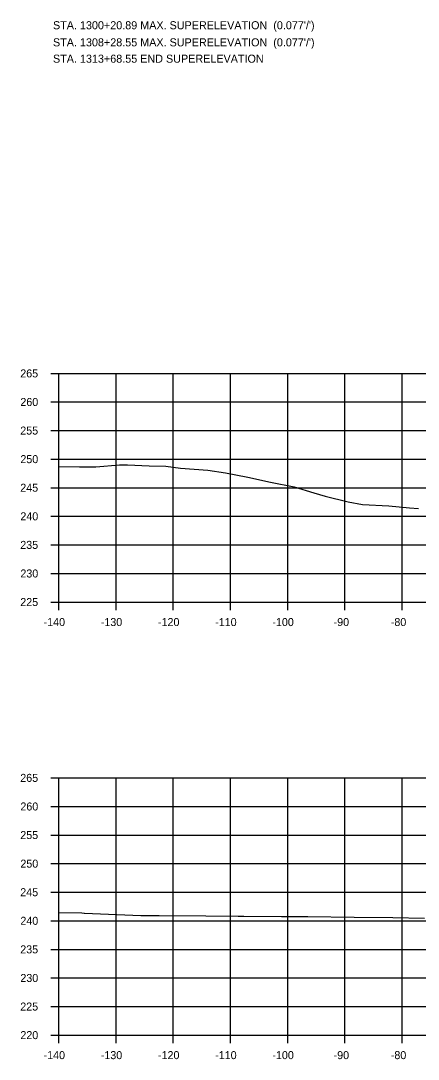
# Model space of a CAD drawing. Extents: x 1342547 to 1344156, y -1532351 to -1517216.
# Drawn here: x 1342556.2 to 1342625.7, y -1520815.1 to -1520633.5 of the extents above; entities that cross this region are included whole.
import ezdxf

# ---------------------------------------------------------------- set-up
doc = ezdxf.new("R2010")
doc.units = 0
for name, color, linetype in [('R_Axis', 7, 'Continuous'), ('R_Axis Annot', 7, 'Continuous'), ('R_Border Notes', 7, 'Continuous'), ('R_Exist Surface', 7, 'Continuous'), ('R_Grid', 7, 'Continuous')]:
    doc.layers.add(name, color=color, linetype=linetype)

msp = doc.modelspace()

# ---------------------------------------------------------------- linework, layer by layer
at = {"layer": 'R_Axis'}
for p, q in [((1342561.47, -1520695.14), (1342562.87, -1520695.14)), ((1342562.87, -1520735.14), (1342562.87, -1520695.14)), ((1342561.47, -1520700.14), (1342562.87, -1520700.14)), ((1342561.47, -1520705.14), (1342562.87, -1520705.14)), ((1342561.47, -1520710.14), (1342562.87, -1520710.14)), ((1342561.47, -1520715.14), (1342562.87, -1520715.14)), ((1342561.47, -1520720.14), (1342562.87, -1520720.14)), ((1342561.47, -1520725.14), (1342562.87, -1520725.14)), ((1342561.47, -1520730.14), (1342562.87, -1520730.14)), ((1342561.47, -1520735.14), (1342562.87, -1520735.14)), ((1342562.87, -1520735.14), (1342842.87, -1520735.14)), ((1342562.87, -1520736.54), (1342562.87, -1520735.14)), ((1342572.87, -1520736.54), (1342572.87, -1520735.14)), ((1342582.87, -1520736.54), (1342582.87, -1520735.14)), ((1342592.87, -1520736.54), (1342592.87, -1520735.14)), ((1342602.87, -1520736.54), (1342602.87, -1520735.14)), ((1342612.87, -1520736.54), (1342612.87, -1520735.14)), ((1342622.87, -1520736.54), (1342622.87, -1520735.14)), ((1342561.47, -1520765.9), (1342562.87, -1520765.9)), ((1342562.87, -1520810.9), (1342562.87, -1520765.9)), ((1342561.47, -1520770.9), (1342562.87, -1520770.9)), ((1342561.47, -1520775.9), (1342562.87, -1520775.9)), ((1342561.47, -1520780.9), (1342562.87, -1520780.9)), ((1342561.47, -1520785.9), (1342562.87, -1520785.9)), ((1342561.47, -1520790.9), (1342562.87, -1520790.9)), ((1342561.47, -1520795.9), (1342562.87, -1520795.9)), ((1342561.47, -1520800.9), (1342562.87, -1520800.9)), ((1342561.47, -1520805.9), (1342562.87, -1520805.9)), ((1342561.47, -1520810.9), (1342562.87, -1520810.9)), ((1342562.87, -1520810.9), (1342842.87, -1520810.9)), ((1342562.87, -1520812.3), (1342562.87, -1520810.9)), ((1342572.87, -1520812.3), (1342572.87, -1520810.9)), ((1342582.87, -1520812.3), (1342582.87, -1520810.9)), ((1342592.87, -1520812.3), (1342592.87, -1520810.9)), ((1342602.87, -1520812.3), (1342602.87, -1520810.9)), ((1342612.87, -1520812.3), (1342612.87, -1520810.9)), ((1342622.87, -1520812.3), (1342622.87, -1520810.9))]:
    msp.add_line(p, q, dxfattribs=at)
at = {"layer": 'R_Exist Surface'}
for points in [[(1342562.87, -1520711.42), (1342566.46, -1520711.46), (1342569.36, -1520711.51), (1342573.45, -1520711.14), (1342574.87, -1520711.15), (1342578.68, -1520711.31), (1342581.55, -1520711.39), (1342584.12, -1520711.71), (1342588.93, -1520712.09), (1342592.02, -1520712.56), (1342595.92, -1520713.29), (1342599.87, -1520714.19), (1342604, -1520714.96), (1342607.42, -1520716.06), (1342609.41, -1520716.6), (1342613.46, -1520717.59), (1342615.97, -1520718.08), (1342620.56, -1520718.32), (1342624.18, -1520718.67), (1342625.73, -1520718.78)], [(1342562.87, -1520789.44), (1342566.87, -1520789.53), (1342567.28, -1520789.54), (1342567.34, -1520789.55), (1342577.17, -1520789.95), (1342580.39, -1520789.96), (1342588.59, -1520790.06), (1342594.24, -1520790.09), (1342595.23, -1520790.08), (1342601.78, -1520790.14), (1342606.37, -1520790.15), (1342614.52, -1520790.29), (1342621.24, -1520790.3), (1342626.8, -1520790.45)]]:
    msp.add_lwpolyline(points, dxfattribs=at)
at = {"layer": 'R_Grid'}
for p, q in [((1342562.87, -1520695.14), (1342842.87, -1520695.14)), ((1342562.87, -1520735.14), (1342562.87, -1520695.14)), ((1342572.87, -1520735.14), (1342572.87, -1520695.14)), ((1342582.87, -1520735.14), (1342582.87, -1520695.14)), ((1342592.87, -1520735.14), (1342592.87, -1520695.14)), ((1342602.87, -1520735.14), (1342602.87, -1520695.14)), ((1342612.87, -1520735.14), (1342612.87, -1520695.14)), ((1342622.87, -1520735.14), (1342622.87, -1520695.14)), ((1342562.87, -1520700.14), (1342842.87, -1520700.14)), ((1342562.87, -1520705.14), (1342842.87, -1520705.14)), ((1342562.87, -1520710.14), (1342842.87, -1520710.14)), ((1342562.87, -1520715.14), (1342842.87, -1520715.14)), ((1342562.87, -1520720.14), (1342842.87, -1520720.14)), ((1342562.87, -1520725.14), (1342842.87, -1520725.14)), ((1342562.87, -1520730.14), (1342842.87, -1520730.14)), ((1342562.87, -1520735.14), (1342842.87, -1520735.14)), ((1342562.87, -1520765.9), (1342842.87, -1520765.9)), ((1342562.87, -1520810.9), (1342562.87, -1520765.9)), ((1342572.87, -1520810.9), (1342572.87, -1520765.9)), ((1342582.87, -1520810.9), (1342582.87, -1520765.9)), ((1342592.87, -1520810.9), (1342592.87, -1520765.9)), ((1342602.87, -1520810.9), (1342602.87, -1520765.9)), ((1342612.87, -1520810.9), (1342612.87, -1520765.9)), ((1342622.87, -1520810.9), (1342622.87, -1520765.9)), ((1342562.87, -1520770.9), (1342842.87, -1520770.9)), ((1342562.87, -1520775.9), (1342842.87, -1520775.9)), ((1342562.87, -1520780.9), (1342842.87, -1520780.9)), ((1342562.87, -1520785.9), (1342842.87, -1520785.9)), ((1342562.87, -1520790.9), (1342842.87, -1520790.9)), ((1342562.87, -1520795.9), (1342842.87, -1520795.9)), ((1342562.87, -1520800.9), (1342842.87, -1520800.9)), ((1342562.87, -1520805.9), (1342842.87, -1520805.9)), ((1342562.87, -1520810.9), (1342842.87, -1520810.9))]:
    msp.add_line(p, q, dxfattribs=at)

# ---------------------------------------------------------------- texts
at = {"layer": 'R_Axis Annot'}
for s, p in [('265', (1342556.12, -1520695.84)), ('260', (1342556.14, -1520700.84)), ('255', (1342556.12, -1520705.84)), ('250', (1342556.14, -1520710.84)), ('245', (1342556.12, -1520715.84)), ('240', (1342556.14, -1520720.84)), ('235', (1342556.12, -1520725.84)), ('230', (1342556.14, -1520730.84)), ('225', (1342556.12, -1520735.84)), ('-140', (1342560.2, -1520739.34)), ('-130', (1342570.2, -1520739.34)), ('-120', (1342580.2, -1520739.34)), ('-110', (1342590.2, -1520739.34)), ('-100', (1342600.2, -1520739.34)), ('-90', (1342610.9, -1520739.34)), ('-80', (1342620.9, -1520739.34)), ('265', (1342556.12, -1520766.6)), ('260', (1342556.14, -1520771.6)), ('255', (1342556.12, -1520776.6)), ('250', (1342556.14, -1520781.6)), ('245', (1342556.12, -1520786.6)), ('240', (1342556.14, -1520791.6)), ('235', (1342556.12, -1520796.6)), ('230', (1342556.14, -1520801.6)), ('225', (1342556.12, -1520806.6)), ('220', (1342556.14, -1520811.6)), ('-140', (1342560.2, -1520815.1)), ('-130', (1342570.2, -1520815.1)), ('-120', (1342580.2, -1520815.1)), ('-110', (1342590.2, -1520815.1)), ('-100', (1342600.2, -1520815.1)), ('-90', (1342610.9, -1520815.1)), ('-80', (1342620.9, -1520815.1))]:
    msp.add_text(s, height=1.4, dxfattribs=at).set_placement(p)
at = {"layer": 'R_Border Notes'}
for s, p in [("STA. 1300+20.89 MAX. SUPERELEVATION  (0.077'/')", (1342561.84, -1520634.94)), ("STA. 1308+28.55 MAX. SUPERELEVATION  (0.077'/')", (1342561.84, -1520637.93)), ('STA. 1313+68.55 END SUPERELEVATION', (1342561.84, -1520640.79))]:
    msp.add_text(s, height=1.41, dxfattribs=at).set_placement(p)

doc.saveas('drawing.dxf')
